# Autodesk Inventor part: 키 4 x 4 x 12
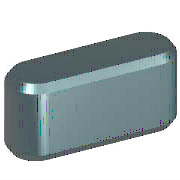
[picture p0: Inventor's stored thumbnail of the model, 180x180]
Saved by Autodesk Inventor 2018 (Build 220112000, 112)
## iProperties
IsCustomPart: 1
Created: 2012-02
Part Number: 키 4 x 4 x 12
Material: 강철, 연강
Description: 키 및 해당 키홈
Document SubType Name: Modeling
Standard: KS B 1311
Designer: mduedu
Standards Organization: KS
Language: ko-KR
Size Designation: 4 x 4 x 12
Categories: <MemberInstance><Categories><Category DisplayName="샤프트 부품" InternalName="7f7aeb1f-a693-4053-b835-cee3144e0d98" Mnemonic="SHFT"><Category DisplayName="키" Interna
Density: 7.86 g/cm^3
Mass: 1.38739 g
Surface Area: 1.94869 cm^2
Volume: 0.176513 cm^3
Appearance: 노란색
Author: mduedu
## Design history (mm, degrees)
workplane "Work Plane1"
workplane "Work Plane2"
sketch "스케치1"
  geometry: L1 (2, 2)-(10, 2); L2 (10, -2)-(2, -2); L3 (0, 9.4)-(0, -7.4) reference; L4 (-5, 0)-(30, 0) reference; L5 (12, 0)-(12, 7); A1 r 2 centre (2, 0) between (2, 2) and (2, -2); A2 r 2 centre (10, 0) between (10, -2) and (10, 2)
  constraints: 6 end point, 5 point on circle, 4 tangent, 3 point on line, 2 centre point, 1 horizontal, 1 parallel, 1 perpendicular
  dimensions: "d0" = 2 radius of A1 (= 0.5 x PB); "d13" = 2 radius of A2 (= 0.5 x PB); "d14" = 12 distance between parallel lines of L5 L3 (= NLG)
extrude "본체1" new body sketch "스케치1" taper "d3" = 0 deg; stored distance "d4" = 10
workplane "Work Plane3"
body "Solid1"
chamfer "모따기1" distance "d8" = 0.25 (= PHH); stored, may be unused: second distance "d9" = 0.25 (= PHH), angle "d15" = 45 deg
other parameters: "d1" = -2.5 (= -PNT), "d2" = 1.5 (= PH - PNT), "NLG" = 12 [user parameter; used in 3 equation terms], "PB" = 4 [user parameter; used in 2 equation terms], "PNT" = 2.5 [user parameter; used in 2 equation terms], "PH" = 4 [user parameter; used in 1 equation term], "PHH" = 0.25 [user parameter; used in 2 equation terms], "d10" = 0, "d16" = 0, "d17" = 0, "d18" = 0, "PLB2" = 12 (= NLG) [user parameter], "WDMAX" = 12 [user parameter], "PLB1" = 12 (= NLG) [user parameter], "RR" = 0.08 [user parameter], "PUEB" = 1.8 [user parameter]
